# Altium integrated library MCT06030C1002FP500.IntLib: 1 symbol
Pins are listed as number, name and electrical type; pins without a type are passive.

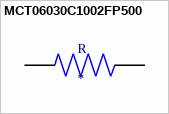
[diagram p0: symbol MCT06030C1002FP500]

## MCT06030C1002FP500
designator R
10 kOhms Â±1% 0.125W, 1/8W Chip Resistor 0603 _1608 Metric_ Anti-Sulfur Thin Film; MP: MCT06030C1002FP500; MF: Vishay Beyschlag
footprint RESC1508X55N
pins: 1, 2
